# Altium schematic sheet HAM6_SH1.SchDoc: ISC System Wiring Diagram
size B; DrawnBy: Filiberto Clara; Engineer: Filiberto Clara; Organization: LIGO Laboratory; Address1: California Institute of Technology; Address2: Massachusetts Institute of Technology; SheetNumber: 26; SheetTotal: 37
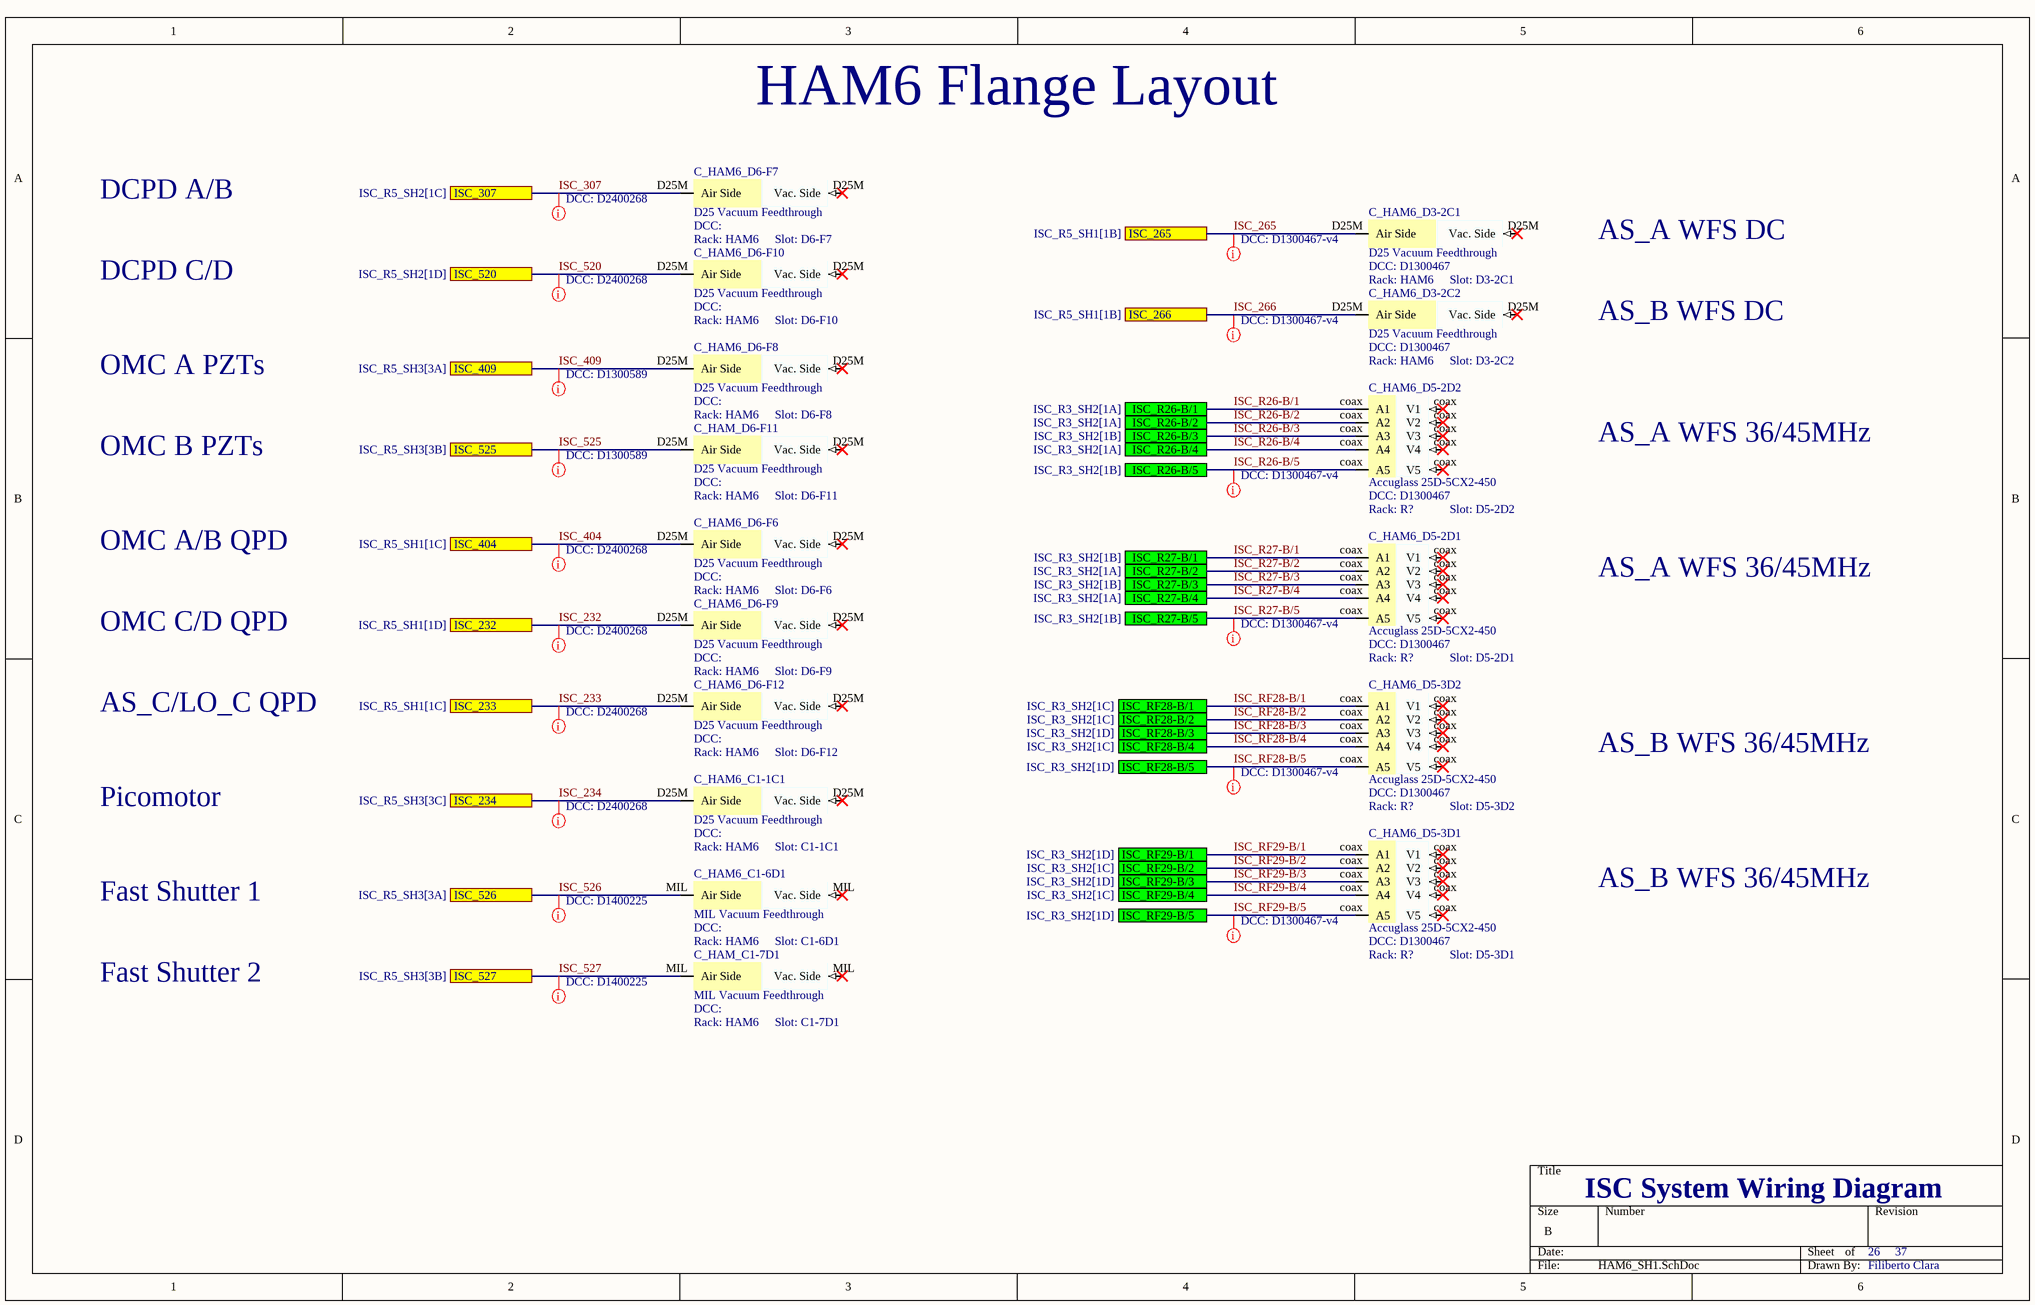
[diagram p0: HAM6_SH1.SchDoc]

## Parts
C_HAM6_C1-1C1  D25 Vacuum Feedthrough  Rack: HAM6  Slot: C1-1C1
C_HAM6_C1-6D1  MIL Vacuum Feedthrough  Rack: HAM6  Slot: C1-6D1
C_HAM6_D3-2C1  D25 Vacuum Feedthrough  DCC: D1300467  Rack: HAM6  Slot: D3-2C1
C_HAM6_D3-2C2  D25 Vacuum Feedthrough  DCC: D1300467  Rack: HAM6  Slot: D3-2C2
C_HAM6_D5-2D1  Accuglass 25D-5CX2-450  DCC: D1300467  Rack: R?  Slot: D5-2D1
C_HAM6_D5-2D2  Accuglass 25D-5CX2-450  DCC: D1300467  Rack: R?  Slot: D5-2D2
C_HAM6_D5-3D1  Accuglass 25D-5CX2-450  DCC: D1300467  Rack: R?  Slot: D5-3D1
C_HAM6_D5-3D2  Accuglass 25D-5CX2-450  DCC: D1300467  Rack: R?  Slot: D5-3D2
C_HAM6_D6-F6  D25 Vacuum Feedthrough  Rack: HAM6  Slot: D6-F6
C_HAM6_D6-F7  D25 Vacuum Feedthrough  Rack: HAM6  Slot: D6-F7
C_HAM6_D6-F8  D25 Vacuum Feedthrough  Rack: HAM6  Slot: D6-F8
C_HAM6_D6-F9  D25 Vacuum Feedthrough  Rack: HAM6  Slot: D6-F9
C_HAM6_D6-F10  D25 Vacuum Feedthrough  Rack: HAM6  Slot: D6-F10
C_HAM6_D6-F12  D25 Vacuum Feedthrough  Rack: HAM6  Slot: D6-F12
C_HAM_C1-7D1  MIL Vacuum Feedthrough  Rack: HAM6  Slot: C1-7D1
C_HAM_D6-F11  D25 Vacuum Feedthrough  Rack: HAM6  Slot: D6-F11

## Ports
ISC_232 (see ISC_R5_SH1[1D]), ISC_233 (see ISC_R5_SH1[1C]), ISC_234 (see ISC_R5_SH3[3C]), ISC_265 (see ISC_R5_SH1[1B]), ISC_266 (see ISC_R5_SH1[1B]), ISC_307 (see ISC_R5_SH2[1C]), ISC_404 (see ISC_R5_SH1[1C]), ISC_409 (see ISC_R5_SH3[3A]), ISC_520 (see ISC_R5_SH2[1D]), ISC_525 (see ISC_R5_SH3[3B]), ISC_526 (see ISC_R5_SH3[3A]), ISC_527 (see ISC_R5_SH3[3B]), ISC_R26-B/1 (see ISC_R3_SH2[1A]), ISC_R26-B/2 (see ISC_R3_SH2[1A]), ISC_R26-B/3 (see ISC_R3_SH2[1B]), ISC_R26-B/4 (see ISC_R3_SH2[1A]), ISC_R26-B/5 (see ISC_R3_SH2[1B]), ISC_R27-B/1 (see ISC_R3_SH2[1B]), ISC_R27-B/2 (see ISC_R3_SH2[1A]), ISC_R27-B/3 (see ISC_R3_SH2[1B]), ISC_R27-B/4 (see ISC_R3_SH2[1A]), ISC_R27-B/5 (see ISC_R3_SH2[1B]), ISC_RF28-B/1 (see ISC_R3_SH2[1C]), ISC_RF28-B/2 (see ISC_R3_SH2[1C]), ISC_RF28-B/3 (see ISC_R3_SH2[1D]), ISC_RF28-B/4 (see ISC_R3_SH2[1C]), ISC_RF28-B/5 (see ISC_R3_SH2[1D]), ISC_RF29-B/1 (see ISC_R3_SH2[1D]), ISC_RF29-B/2 (see ISC_R3_SH2[1C]), ISC_RF29-B/3 (see ISC_R3_SH2[1D]), ISC_RF29-B/4 (see ISC_R3_SH2[1C]), ISC_RF29-B/5 (see ISC_R3_SH2[1D])

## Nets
ISC_232: C_HAM6_D6-F9.D25M(Vac._Side) ; port ISC_232
ISC_233: C_HAM6_D6-F12.D25M(Vac._Side) ; port ISC_233
ISC_234: C_HAM6_C1-1C1.D25M(Vac._Side) ; port ISC_234
ISC_265: C_HAM6_D3-2C1.D25M(Vac._Side) ; port ISC_265
ISC_266: C_HAM6_D3-2C2.D25M(Vac._Side) ; port ISC_266
ISC_307: C_HAM6_D6-F7.D25M(Vac._Side) ; port ISC_307
ISC_404: C_HAM6_D6-F6.D25M(Vac._Side) ; port ISC_404
ISC_409: C_HAM6_D6-F8.D25M(Vac._Side) ; port ISC_409
ISC_520: C_HAM6_D6-F10.D25M(Vac._Side) ; port ISC_520
ISC_525: C_HAM_D6-F11.D25M(Vac._Side) ; port ISC_525
ISC_526: C_HAM6_C1-6D1.MIL(Vac._Side) ; port ISC_526
ISC_527: C_HAM_C1-7D1.MIL(Vac._Side) ; port ISC_527
ISC_R26-B/1: C_HAM6_D5-2D2.coax(V1) ; port ISC_R26-B/1
ISC_R26-B/2: C_HAM6_D5-2D2.coax(A2) ; port ISC_R26-B/2
ISC_R26-B/3: C_HAM6_D5-2D2.coax(A3) ; port ISC_R26-B/3
ISC_R26-B/4: C_HAM6_D5-2D2.coax(A4) ; port ISC_R26-B/4
ISC_R26-B/5: C_HAM6_D5-2D2.coax(A5) ; port ISC_R26-B/5
ISC_R27-B/1: C_HAM6_D5-2D1.coax(V1) ; port ISC_R27-B/1
ISC_R27-B/2: C_HAM6_D5-2D1.coax(A2) ; port ISC_R27-B/2
ISC_R27-B/3: C_HAM6_D5-2D1.coax(A3) ; port ISC_R27-B/3
ISC_R27-B/4: C_HAM6_D5-2D1.coax(A4) ; port ISC_R27-B/4
ISC_R27-B/5: C_HAM6_D5-2D1.coax(A5) ; port ISC_R27-B/5
ISC_RF28-B/1: C_HAM6_D5-3D2.coax(V1) ; port ISC_RF28-B/1
ISC_RF28-B/2: C_HAM6_D5-3D2.coax(A2) ; port ISC_RF28-B/2
ISC_RF28-B/3: C_HAM6_D5-3D2.coax(A3) ; port ISC_RF28-B/3
ISC_RF28-B/4: C_HAM6_D5-3D2.coax(A4) ; port ISC_RF28-B/4
ISC_RF28-B/5: C_HAM6_D5-3D2.coax(A5) ; port ISC_RF28-B/5
ISC_RF29-B/1: C_HAM6_D5-3D1.coax(V1) ; port ISC_RF29-B/1
ISC_RF29-B/2: C_HAM6_D5-3D1.coax(A2) ; port ISC_RF29-B/2
ISC_RF29-B/3: C_HAM6_D5-3D1.coax(A3) ; port ISC_RF29-B/3
ISC_RF29-B/4: C_HAM6_D5-3D1.coax(A4) ; port ISC_RF29-B/4
ISC_RF29-B/5: C_HAM6_D5-3D1.coax(A5) ; port ISC_RF29-B/5

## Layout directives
DCC: D1300467-v4: ISC_265, ISC_266, ISC_R26-B/5, ISC_R27-B/5, ISC_RF28-B/5, ISC_RF29-B/5
DCC: D2400268: ISC_232, ISC_233, ISC_234, ISC_307, ISC_404, ISC_520
DCC: D1300589: ISC_409, ISC_525
DCC: D1400225: ISC_526, ISC_527

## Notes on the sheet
- HAM6 Flange Layout
- DCPD A/B
- AS_A WFS DC
- DCPD C/D
- OMC A PZTs
- AS_B WFS DC
- AS_A WFS 36/45MHz
- OMC B PZTs
- OMC A/B QPD
- OMC C/D QPD
- AS_C/LO_C QPD
- AS_B WFS 36/45MHz
- Picomotor
- Fast Shutter 1
- Fast Shutter 2

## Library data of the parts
C_HAM6_C1-1C1 C_HAM6_C1-6D1 C_HAM6_D3-2C1 C_HAM6_D3-2C2 C_HAM6_D6-F6-C_HAM6_D6-F10 C_HAM6_D6-F12 C_HAM_C1-7D1 C_HAM_D6-F11 = VacFeedD25: Serial: Sxxxxxxx; System: ISC
C_HAM6_D5-2D1 C_HAM6_D5-2D2 C_HAM6_D5-3D1 C_HAM6_D5-3D2 = Vac.Feed Coax DB 5W5: Vac.Feed Coax Dsub DB5W5; System: ISC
